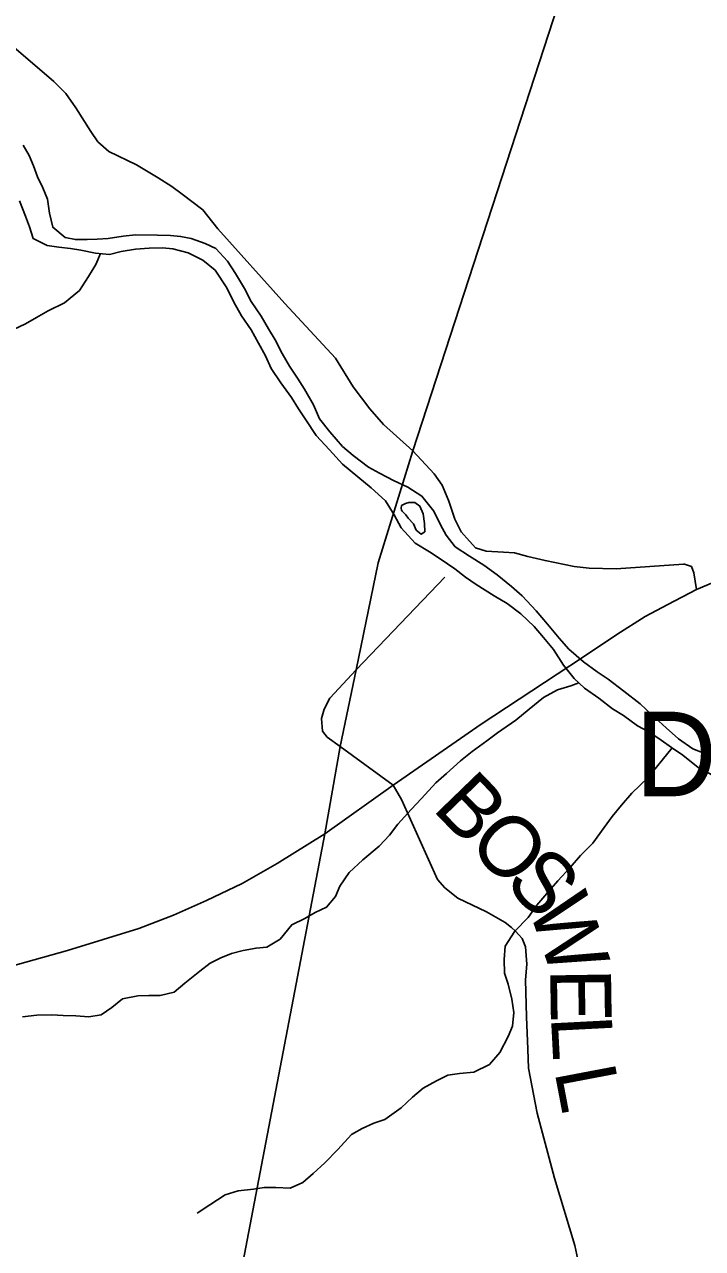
# Model space of a CAD drawing. Extents: x 1578669 to 1989827, y 208020 to 553079.
# Drawn here: x 1807123 to 1810467, y 400300 to 406335 of the extents above; entities that cross this region are included whole.
import ezdxf

# ---------------------------------------------------------------- set-up
doc = ezdxf.new("R2010")
doc.units = 0
for name, color, linetype in [('GM_X_County_Road', 7, 'Continuous'), ('GM_X_Major_River', 7, 'Continuous'), ('GM_X_Minor_River', 7, 'Continuous'), ('GM_X_State_Route', 7, 'Continuous'), ('GM_X_Township', 7, 'Continuous'), ('GM_X_Township_Road', 7, 'Continuous'), ('GM_X_Township_Road_Text', 7, 'Continuous'), ('GM_X_Unincorporated_Text', 7, 'Continuous')]:
    doc.layers.add(name, color=color, linetype=linetype)

msp = doc.modelspace()

# ---------------------------------------------------------------- linework, layer by layer
at = {"layer": 'GM_X_County_Road'}
for points in [[(1807071.4, 406221), (1807161.8, 406144.6), (1807268.2, 406054.2), (1807326.4, 405993.9), (1807376.5, 405923.6), (1807450.8, 405807.1), (1807484.9, 405756.9), (1807539.1, 405708.7), (1807675.6, 405642.3), (1807782.1, 405578), (1807850.4, 405535.8), (1807900.6, 405497.6), (1808002.9, 405421.2), (1808077.2, 405326.8), (1808406.4, 404959.2), (1808656.1, 404690), (1808743.5, 404547.7), (1808826.8, 404440), (1808892.8, 404361.8), (1809037.4, 404232.9), (1809143.8, 404118.9), (1809182.4, 404063), (1809215, 403984.1), (1809245.3, 403895.5), (1809276.7, 403832.7), (1809317.1, 403786.7), (1809333.6, 403769.6)], [(1809333.6, 403769.6), (1809347.4, 403755.2), (1809400.1, 403738.4), (1809485.4, 403733.9), (1809539.3, 403729.4), (1809605.4, 403711.5), (1809690.7, 403691.3), (1809834.3, 403663.2), (1809907.2, 403654.3), (1810040.7, 403650.9), (1810372.4, 403674)], [(1810372.4, 403674), (1810378.4, 403674.5), (1810412.1, 403662.1), (1810424.4, 403631.8), (1810436.7, 403548.8)]]:
    msp.add_lwpolyline(points, dxfattribs=at)
at = {"layer": 'GM_X_Major_River'}
for points in [[(1807115.9, 405740.5), (1807145.7, 405688.2), (1807167.4, 405638), (1807187.2, 405583.8), (1807212.9, 405529.5), (1807236.6, 405473.3), (1807246.3, 405405.1), (1807261.9, 405334.8), (1807323.8, 405284.4), (1807373.8, 405274.2), (1807431.8, 405273.9), (1807481.9, 405275.7), (1807536, 405279.5), (1807610.1, 405291.1), (1807670.2, 405296.9), (1807778.4, 405296.4), (1807842.4, 405294.1), (1807892.5, 405289.9), (1807944.5, 405279.6), (1808014.4, 405255.3), (1808066.4, 405231), (1808124.1, 405168.5), (1808163.8, 405106.2), (1808207.5, 405033.8), (1808241.2, 404969.5), (1808290.9, 404897.1), (1808326.6, 404834.8), (1808358.4, 404780.5), (1808394.1, 404712.2), (1808429.8, 404649.9), (1808469.5, 404591.5), (1808503.3, 404537.2), (1808548.9, 404458.8), (1808578.6, 404390.5), (1808628.3, 404326.1), (1808692, 404253.7), (1808743.9, 404209.3), (1808819.7, 404152.8), (1808873.6, 404122.5), (1808943.5, 404086.1), (1809013.4, 404053.7), (1809083.2, 404009.3), (1809140.9, 403934.9), (1809174.6, 403868.5), (1809202.4, 403816.3), (1809246.1, 403760), (1809318, 403713.5), (1809387.8, 403669.1), (1809453.7, 403620.7), (1809525.4, 403564.2), (1809577.3, 403517.8), (1809647, 403443.3), (1809702.7, 403378.9), (1809760.4, 403308.5), (1809808.2, 403254.1), (1809879.9, 403191.7), (1809947.8, 403143.2), (1810001.6, 403106.9), (1810079.4, 403048.4), (1810159.2, 402985.9)], [(1807098.4, 405465.9), (1807128.1, 405389.5), (1807147.8, 405337.3), (1807165.5, 405279.1), (1807235.4, 405244.7), (1807291.5, 405236.4), (1807349.5, 405230.2), (1807401.5, 405221.9), (1807473.5, 405207.5), (1807541.6, 405201.2), (1807599.7, 405215), (1807669.9, 405226.7), (1807738, 405232.4), (1807804.1, 405234.1), (1807854.1, 405227.9), (1807930.1, 405209.5), (1808002, 405173.1), (1808063.8, 405122.7), (1808121.4, 405036.2), (1808155.1, 404965.9), (1808192.8, 404897.6), (1808240.5, 404829.2), (1808276.2, 404762.8), (1808311.9, 404700.5), (1808339.6, 404638.2), (1808387.3, 404567.8), (1808439, 404495.4), (1808474.7, 404439.1), (1808510.5, 404384.8), (1808562.2, 404308.4), (1808627.9, 404237.9), (1808691.6, 404167.5), (1808767.3, 404105), (1808833.1, 404050.5), (1808902.9, 403986.1), (1808946.6, 403917.7), (1808980.3, 403853.4), (1809050, 403776.9), (1809119.8, 403734.5), (1809173.7, 403700.1), (1809245.6, 403651.7), (1809297.4, 403609.3), (1809351.3, 403573), (1809439.1, 403518.5), (1809503, 403480.1), (1809570.8, 403429.6), (1809636.5, 403367.2), (1809682.3, 403312.9), (1809732.1, 403252.5), (1809781.7, 403176.1), (1809833.4, 403109.7), (1809885.3, 403063.3), (1809955.1, 403012.9)], [(1808982.5, 403963.5), (1808981, 403950.4), (1808982.8, 403940), (1808985.5, 403935.4), (1809002.8, 403917.5)], [(1809002.8, 403917.5), (1809014.9, 403901.5), (1809041, 403873.6), (1809055.2, 403841.6), (1809079.3, 403821.7), (1809097.3, 403833.8), (1809095.1, 403873.9), (1809088.9, 403922), (1809072.7, 403960), (1809048.6, 403977.9), (1809018.5, 403977.7), (1809002.5, 403973.6), (1808982.5, 403963.5)], [(1810515.8, 402633.4), (1810445.9, 402671.8), (1810370.1, 402732.3), (1810314.3, 402770.6), (1810262.4, 402807), (1810204.5, 402845.3), (1810146.6, 402877.7), (1810076.8, 402928.1), (1810022.9, 402960.4), (1809955.1, 403012.9)], [(1809955.1, 403012.9), (1810022.9, 402960.4), (1810076.8, 402928.1), (1810146.6, 402877.7), (1810204.5, 402845.3), (1810262.4, 402807), (1810314.3, 402770.6), (1810370.1, 402732.3), (1810445.9, 402671.8), (1810515.8, 402633.4)], [(1810159.2, 402985.9), (1810215, 402933.5), (1810286.7, 402867), (1810348.5, 402812.6), (1810418.3, 402764.1), (1810494.3, 402733.7)], [(1810159.2, 402985.9), (1810215, 402933.5), (1810286.7, 402867), (1810348.5, 402812.6), (1810418.3, 402764.1), (1810494.3, 402733.7)]]:
    msp.add_lwpolyline(points, dxfattribs=at)
at = {"layer": 'GM_X_Minor_River'}
for points in [[(1807498.3, 405205.3), (1807475.1, 405152), (1807439.3, 405091.7), (1807393.5, 405023.3), (1807319.7, 404962.8), (1807239.8, 404922.3), (1807181.8, 404889.9), (1807127.9, 404859.5), (1807067.9, 404831.1)], [(1809857, 403088.6), (1809817.7, 403074), (1809751.7, 403053.6), (1809681.8, 403017.1), (1809611.9, 402958.6), (1809546.1, 402904.2), (1809456.2, 402841.6), (1809402.3, 402803.2), (1809330.5, 402750.7), (1809272.6, 402704.3), (1809204.8, 402641.8), (1809150.9, 402595.4), (1809081.2, 402518.8), (1809029.3, 402464.5), (1808963.6, 402391.9), (1808923.8, 402337.6), (1808871.9, 402283.2), (1808792.1, 402216.6), (1808724.3, 402154.1), (1808678.6, 402085.7), (1808656.8, 402035.5), (1808612.9, 401983.2), (1808557, 401956.8), (1808505, 401926.5), (1808441.1, 401896.1), (1808383.3, 401825.6), (1808317.4, 401785.2), (1808265.4, 401780.9), (1808201.3, 401768.5), (1808143.3, 401754.2), (1808091.3, 401733.8), (1808039.4, 401707.5), (1807987.5, 401667.1), (1807913.6, 401608.6), (1807861.8, 401564.2), (1807791.8, 401547.8), (1807735.7, 401547.5), (1807681.6, 401545.2), (1807605.6, 401530.8), (1807553.7, 401488.4), (1807501.8, 401452.1), (1807439.7, 401441.7), (1807375.6, 401447.4), (1807313.5, 401449.1), (1807257.4, 401452.8), (1807183.3, 401450.4), (1807113.3, 401442)], [(1810316.4, 402769.1), (1810196.3, 402621), (1810118.5, 402544.4), (1810066.7, 402486), (1810020.9, 402429.7), (1809981.1, 402375.3), (1809925.4, 402298.9), (1809865.5, 402238.4), (1809813.7, 402178), (1809753.9, 402113.5), (1809708.1, 402061.2), (1809650.3, 401992.7), (1809606.6, 401932.3), (1809540.8, 401863.9), (1809493, 401791.4), (1809489.3, 401725.3), (1809489.6, 401657.1), (1809507.9, 401603.1), (1809526.3, 401529), (1809536.6, 401463), (1809528.9, 401396.8), (1809509.1, 401344.5), (1809467.4, 401266.1), (1809415.6, 401207.8), (1809339.6, 401169.3), (1809267.6, 401162.9), (1809211.5, 401154.5), (1809155.6, 401126.2), (1809089.6, 401089.8), (1809035.8, 401045.4), (1808979.9, 400993), (1808900.1, 400936.4), (1808846.1, 400918.1), (1808788.1, 400891.7), (1808736.2, 400861.4), (1808668.4, 400788.8), (1808604.6, 400722.4), (1808546.8, 400670), (1808494.9, 400625.6), (1808432.9, 400597.2), (1808362.8, 400600.8), (1808304.7, 400600.5), (1808252.7, 400592.2), (1808176.6, 400583.8), (1808112.6, 400565.4), (1808036.8, 400514.9), (1807974.9, 400474.5)]]:
    msp.add_lwpolyline(points, dxfattribs=at)
at = {"layer": 'GM_X_State_Route'}
msp.add_lwpolyline([(1807047.9, 401689), (1807335.7, 401769.8), (1807687.1, 401878), (1807857.1, 401943.6), (1808021, 402015.6), (1808195.8, 402098.9), (1808369.1, 402198.1), (1808603.5, 402343.9), (1808941.6, 402584.6), (1809374.6, 402885), (1809875, 403214.6), (1810044.1, 403327.8), (1810183.2, 403416.4), (1810296.5, 403475.9), (1810436.7, 403548.8), (1810551.2, 403597.1)], dxfattribs=at)
at = {"layer": 'GM_X_Township'}
for points in [[(1794613.6, 432491), (1800877.7, 431987.5), (1805342.9, 431618.8), (1806251.4, 431555.7), (1812295.7, 431153.9), (1812748.1, 423763.1), (1812980.7, 420551.4), (1813182.7, 417646.4), (1813168.5, 417494.8), (1813100.6, 417317.5), (1811396.3, 411351.9), (1811003, 410233.1), (1810652.7, 409191.2), (1809037.4, 404232.9), (1808867.4, 403681), (1808758.2, 403152.3), (1808679.5, 402774.7), (1808603.5, 402343.9), (1807249.9, 395260.6), (1804835, 395343.7), (1793084.6, 395748)], [(1817084.3, 393898.6), (1817267.6, 394775.1), (1817352.8, 395143.3), (1807249.9, 395260.6), (1808603.5, 402343.9), (1808679.5, 402774.7), (1808758.2, 403152.3), (1808867.4, 403681), (1809037.4, 404232.9), (1810652.7, 409191.2), (1811003, 410233.1), (1811396.3, 411351.9), (1813100.6, 417317.5)]]:
    msp.add_lwpolyline(points, dxfattribs=at)
at = {"layer": 'GM_X_Township_Road'}
for points in [[(1809196, 403610.5), (1808758.2, 403152.3), (1808628.8, 403013.2), (1808600.2, 402958.5), (1808588, 402913.9), (1808592.1, 402850.9), (1808616.4, 402820.4), (1808679.5, 402774.7), (1808941.6, 402584.6), (1808982.2, 402513.5), (1809159, 402119.3), (1809195.6, 402078.6), (1809260.7, 402027.8), (1809400.9, 401960.7), (1809494.3, 401907.9), (1809525.1, 401882.1)], [(1809525.1, 401882.1), (1809545.1, 401865.2), (1809577.7, 401828.7), (1809593.9, 401788), (1809600, 401702.7), (1809593.4, 401625.4), (1809599.4, 401442.7), (1809605.3, 401282.1), (1809609.2, 401189.7), (1809651.3, 400966.8), (1809737.5, 400647.6), (1809837.7, 400314.2), (1809885.7, 400085.3)]]:
    msp.add_lwpolyline(points, dxfattribs=at)

# ---------------------------------------------------------------- texts
at = {"layer": 'GM_X_Township_Road_Text'}
for s, rotation, p in [('B', 314.01196, (1809128.7, 402466.9)), ('O', 314.00829, (1809299.9, 402289.7)), ('S', 313.84417, (1809483.2, 402100)), ('W', 289.13403, (1809605.7, 401983)), ('E', 270.88287, (1809715.2, 401679.4)), ('L', 272.98238, (1809719.1, 401443)), ('L', 280.76625, (1809736.1, 401174.7))]:
    msp.add_text(s, height=300, rotation=rotation, dxfattribs=at).set_placement(p)
at = {"layer": 'GM_X_Unincorporated_Text'}
msp.add_text('Daleyville', height=417, rotation=0.00001, dxfattribs=at).set_placement((1810134.9, 402529.8))

doc.saveas('drawing.dxf')
